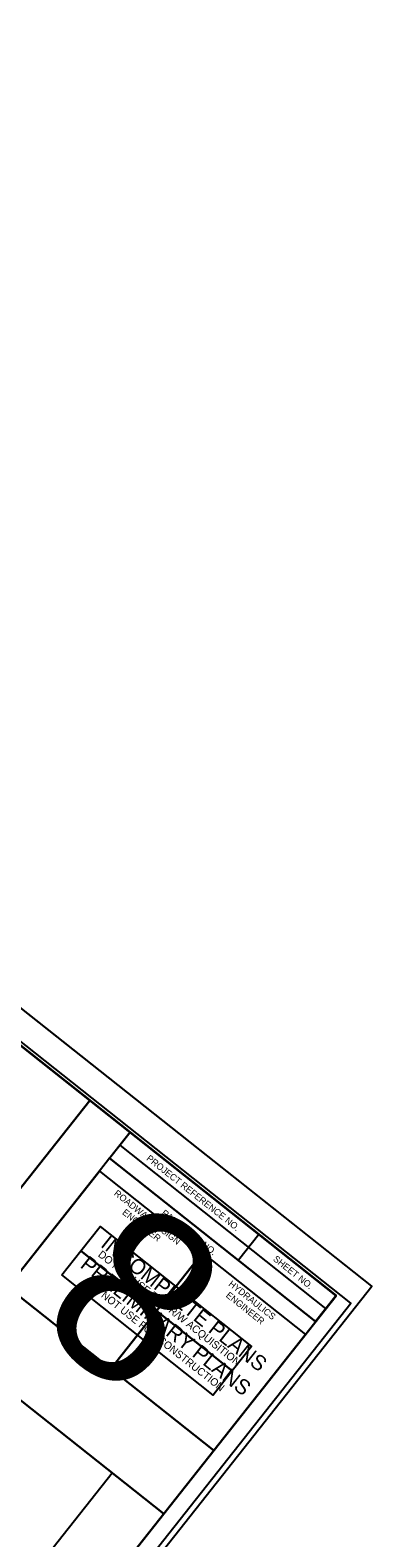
# Model space of a CAD drawing. Extents: x 1778994 to 1784559, y 810461 to 816654.
# Drawn here: x 1783653 to 1783913, y 813902 to 815048 of the extents above; entities that cross this region are included whole.
import ezdxf

# ---------------------------------------------------------------- set-up
doc = ezdxf.new("R2010")
doc.units = 0
for name, color, linetype in [('Sheet Clip Boundary CELL', 7, 'Continuous'), ('Sheet Cutting Line CELL', 7, 'Continuous'), ('Sheet Layout Plan Border', 7, 'Continuous'), ('Sheet Plan CELL', 7, 'Continuous'), ('Sheet Plan Layout CELL', 7, 'Continuous'), ('Sheet Plot Border Inside CELL', 7, 'Continuous'), ('Sheet Plot Border Outside CELL', 7, 'Continuous'), ('Sheet Sticker Incomplete CELL', 7, 'Continuous'), ('Sheet Sticker Preliminary CELL', 7, 'Continuous')]:
    doc.layers.add(name, color=color, linetype=linetype)

msp = doc.modelspace()

# ---------------------------------------------------------------- linework, layer by layer
at = {"layer": 'Sheet Clip Boundary CELL'}
msp.add_lwpolyline([(1782097.5, 814162.5), (1783195.2, 813293.5), (1783715.7, 813950.9), (1783567.3, 814068.4), (1783698.6, 814234.2), (1782749.3, 814985.7)], close=True, dxfattribs=at)
at = {"layer": 'Sheet Cutting Line CELL'}
msp.add_line((1783913.4, 814092.8), (1782593.5, 815137.7), dxfattribs=at)
at = {"layer": 'Sheet Layout Plan Border'}
msp.add_lwpolyline([(1782097.5, 814162.5), (1783195.2, 813293.5), (1783715.7, 813950.9), (1783567.3, 814068.4), (1783698.6, 814234.2), (1782749.3, 814985.7)], close=True, dxfattribs=at)
at = {"layer": 'Sheet Plan CELL'}
for p, q in [((1783713.7, 814190.2), (1783706, 814180.4)), ((1783713.7, 814190.2), (1783870.6, 814066)), ((1783713.7, 814190.2), (1783870.6, 814066)), ((1783721.5, 814200), (1783878.3, 814075.8)), ((1783827.3, 814132.2), (1783811.8, 814112.6)), ((1783784.4, 814118.3), (1783714.6, 814030.1))]:
    msp.add_line(p, q, dxfattribs=at)
for points in [[(1783886.2, 814085.7), (1782710.1, 815016.8), (1782058.3, 814193.5), (1783234.4, 813262.4)], [(1782058.3, 814193.5), (1782710.1, 815016.8), (1783729.3, 814209.9), (1783636.2, 814092.2), (1783793, 813968), (1783234.4, 813262.4)], [(1783729.3, 814209.9), (1783886.2, 814085.7), (1783870.6, 814066), (1783713.7, 814190.2)], [(1783706, 814180.4), (1783784.4, 814118.3), (1783714.6, 814030.1), (1783636.2, 814092.2)], [(1783784.4, 814118.3), (1783862.8, 814056.2), (1783793, 813968), (1783714.6, 814030.1)]]:
    msp.add_lwpolyline(points, close=True, dxfattribs=at)
at = {"layer": 'Sheet Plan Layout CELL'}
for points in [[(1782710.1, 815016.8), (1782058.3, 814193.5), (1783234.4, 813262.4), (1783754.9, 813919.9), (1783567.3, 814068.4), (1783698.6, 814234.2)], [(1783567.3, 814068.4), (1783754.9, 813919.9), (1783886.2, 814085.6), (1783698.6, 814234.2)]]:
    msp.add_lwpolyline(points, close=True, dxfattribs=at)
at = {"layer": 'Sheet Plot Border Inside CELL'}
msp.add_lwpolyline([(1781936.4, 814286.8), (1783242.6, 813252.7), (1783897.5, 814079.9), (1782591.3, 815114)], close=True, dxfattribs=at)
at = {"layer": 'Sheet Plot Border Outside CELL'}
msp.add_lwpolyline([(1781913.8, 814279.2), (1783233.7, 813234.2), (1783913.4, 814092.8), (1782593.5, 815137.7)], close=True, dxfattribs=at)
at = {"layer": 'Sheet Sticker Incomplete CELL'}
msp.add_lwpolyline([(1783691.9, 814119.8), (1783706.5, 814138.2), (1783821.7, 814047), (1783807.1, 814028.6)], close=True, dxfattribs=at)
at = {"layer": 'Sheet Sticker Preliminary CELL'}
msp.add_lwpolyline([(1783677.3, 814101.4), (1783691.9, 814119.8), (1783807.1, 814028.6), (1783792.5, 814010.1)], close=True, dxfattribs=at)

# ---------------------------------------------------------------- texts
at = {"layer": 'Sheet Plan CELL'}
for s, p in [('PROJECT REFERENCE NO.', (1783741.3, 814189.2)), ('ROADWAY DESIGN', (1783716.6, 814162.6)), ('ENGINEER', (1783722.9, 814148.1)), ('R/W SHEET NO.', (1783752.7, 814147.6)), ('SHEET NO.', (1783837.8, 814112.7)), ('HYDRAULICS', (1783803.8, 814093.7)), ('ENGINEER', (1783801.8, 814085.1))]:
    msp.add_text(s, height=5, rotation=321.6309, dxfattribs=at).set_placement(p)
at = {"layer": 'Sheet Plan Layout CELL'}
msp.add_text('8', height=131.3, rotation=321.6309, dxfattribs=at).set_placement((1783654.2, 814063.9))
at = {"layer": 'Sheet Sticker Incomplete CELL'}
for s, height, p in [('INCOMPLETE PLANS', 11.52, (1783706.2, 814123.4)), ('DO NOT USE FOR R/W ACQUISITION', 5.76, (1783704.4, 814116))]:
    msp.add_text(s, height=height, rotation=321.6309, dxfattribs=at).set_placement(p)
at = {"layer": 'Sheet Sticker Preliminary CELL'}
for s, height, p in [('PRELIMINARY PLANS', 11.52, (1783690.6, 814107.7)), ('DO NOT USE FOR CONSTRUCTION', 5.76, (1783696, 814093.5))]:
    msp.add_text(s, height=height, rotation=321.6309, dxfattribs=at).set_placement(p)

doc.saveas('drawing.dxf')
